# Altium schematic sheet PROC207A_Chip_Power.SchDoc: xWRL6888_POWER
size 431 x 279 mm; Date: Not shown in title block; ApprovedBy: Not shown in title block; CheckedBy: Not shown in title block; Author: Not shown in title block; CompanyName: Not shown in title block; DrawnBy: Mistral; Engineer: Not shown in title block; Organization: Not shown in title block; Address1: Not shown in title block; Address2: Not shown in title block; Address3: Not shown in title block; Address4: Not shown in title block; DocumentNumber: 2; Revision: Use project parameter SCH_Rev; SheetNumber: 7; SheetTotal: 18; PageSetup: Record=PageOptions¦CenterHorizontal=True¦CenterVertical=True¦PrintScale=1.00¦XCorrection=1.00¦YCorrection=1.00¦PrintKind=0¦BorderSize=5000000¦LeftOffset=0¦BottomOffset=0¦Orientation=2¦PaperLength=1000¦PaperWidth=1000¦Scale=100¦PaperSource=15¦PrintQuality=600¦MediaType=1¦DitherType=10¦PaperKind=Letter¦PrintScaleMode=1
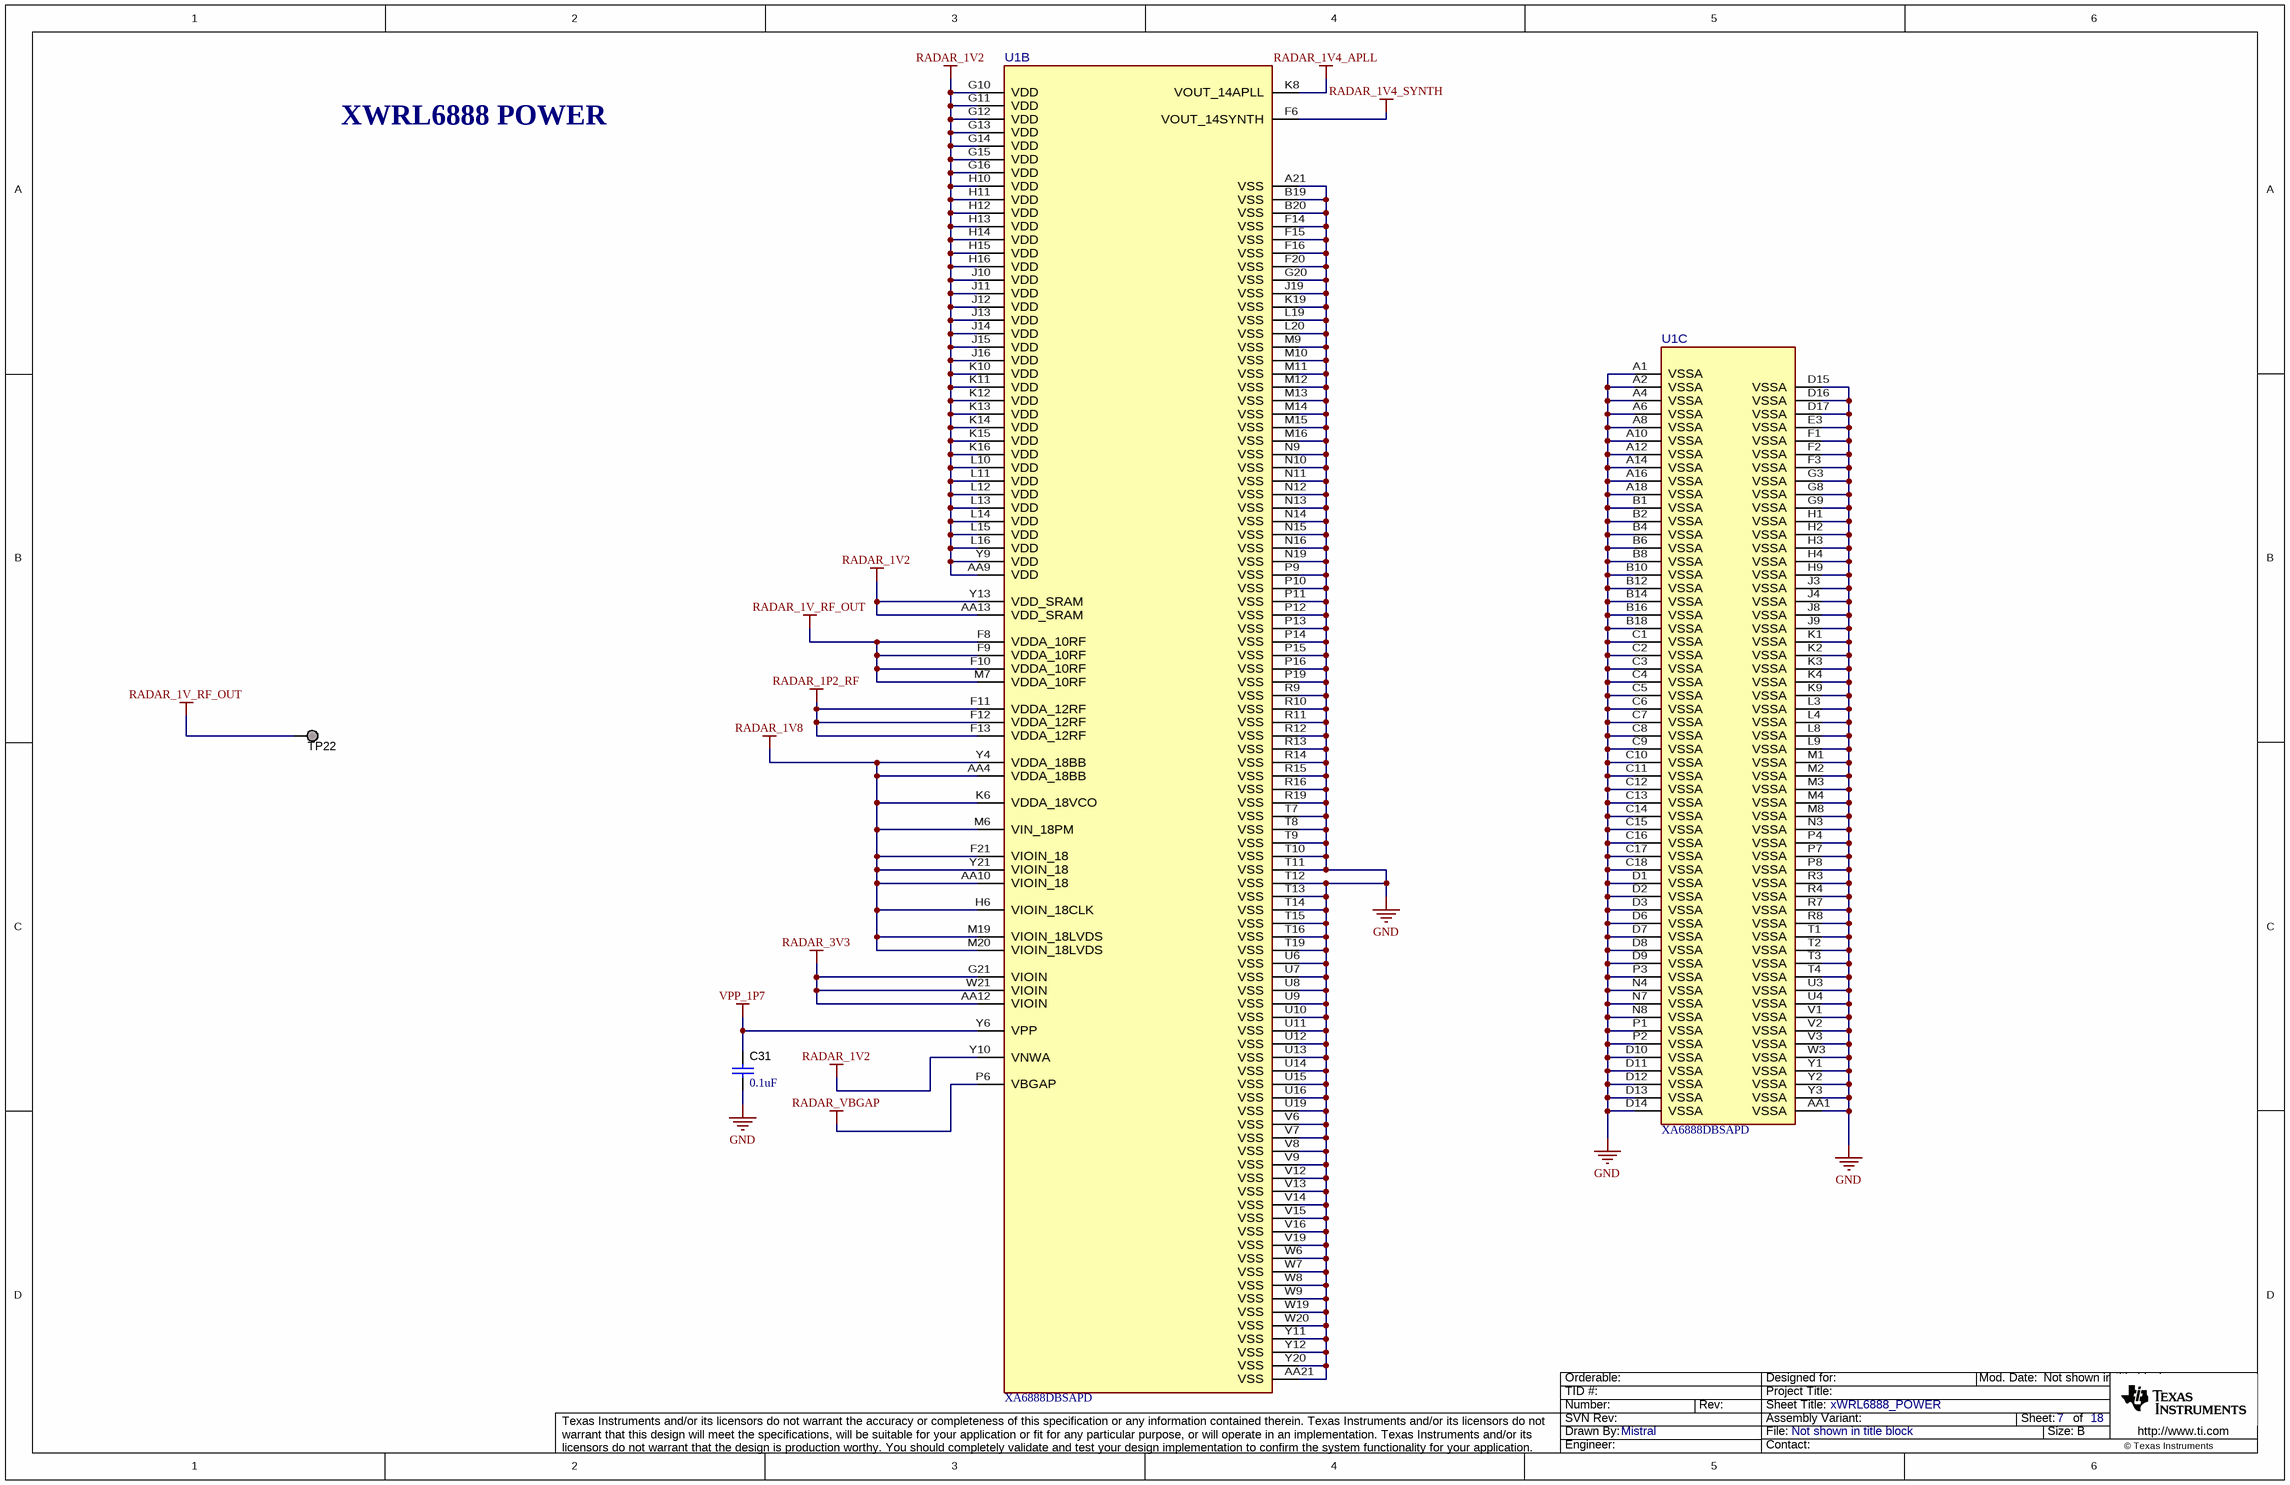
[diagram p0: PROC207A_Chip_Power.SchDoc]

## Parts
C31  ValueDisplayed: 0.1uF  [0402]  (hidden comment: GCM155R71H104KE02D)
TP22  TESTPOINT  [TP_VIA_060RND040]  (value not drawn)  (no BOM)
U1  XA6888DBSAPD  [0-MFG]  (parts B,C of 3)

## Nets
GND: C31.2 U1.A1(VSSA) U1.A2(VSSA) U1.A4(VSSA) U1.A6(VSSA) U1.A8(VSSA) U1.A10(VSSA) U1.A12(VSSA) U1.A14(VSSA) U1.A16(VSSA) U1.A18(VSSA) U1.A21(VSS) U1.AA1(VSSA) U1.AA21(VSS) U1.B1(VSSA) U1.B2(VSSA) U1.B4(VSSA) U1.B6(VSSA) U1.B8(VSSA) U1.B10(VSSA) U1.B12(VSSA) U1.B14(VSSA) U1.B16(VSSA) U1.B18(VSSA) U1.B19(VSS) U1.B20(VSS) U1.C1(VSSA) U1.C2(VSSA) U1.C3(VSSA) U1.C4(VSSA) U1.C5(VSSA) U1.C6(VSSA) U1.C7(VSSA) U1.C8(VSSA) U1.C9(VSSA) U1.C10(VSSA) U1.C11(VSSA) U1.C12(VSSA) U1.C13(VSSA) U1.C14(VSSA) U1.C15(VSSA) U1.C16(VSSA) U1.C17(VSSA) U1.C18(VSSA) U1.D1(VSSA) U1.D2(VSSA) U1.D3(VSSA) U1.D6(VSSA) U1.D7(VSSA) U1.D8(VSSA) U1.D9(VSSA) U1.D10(VSSA) U1.D11(VSSA) U1.D12(VSSA) U1.D13(VSSA) U1.D14(VSSA) U1.D15(VSSA) U1.D16(VSSA) U1.D17(VSSA) U1.E3(VSSA) U1.F1(VSSA) U1.F2(VSSA) U1.F3(VSSA) U1.F14(VSS) U1.F15(VSS) U1.F16(VSS) U1.F20(VSS) U1.G3(VSSA) U1.G8(VSSA) U1.G9(VSSA) U1.G20(VSS) U1.H1(VSSA) U1.H2(VSSA) U1.H3(VSSA) U1.H4(VSSA) U1.H9(VSSA) U1.J3(VSSA) U1.J4(VSSA) U1.J8(VSSA) U1.J9(VSSA) U1.J19(VSS) U1.K1(VSSA) U1.K2(VSSA) U1.K3(VSSA) U1.K4(VSSA) U1.K9(VSSA) U1.K19(VSS) U1.L3(VSSA) U1.L4(VSSA) U1.L8(VSSA) U1.L9(VSSA) U1.L19(VSS) U1.L20(VSS) U1.M1(VSSA) U1.M2(VSSA) U1.M3(VSSA) U1.M4(VSSA) U1.M8(VSSA) U1.M9(VSS) U1.M10(VSS) U1.M11(VSS) U1.M12(VSS) U1.M13(VSS) U1.M14(VSS) U1.M15(VSS) U1.M16(VSS) U1.N3(VSSA) U1.N4(VSSA) U1.N7(VSSA) U1.N8(VSSA) U1.N9(VSS) U1.N10(VSS) U1.N11(VSS) U1.N12(VSS) U1.N13(VSS) U1.N14(VSS) U1.N15(VSS) U1.N16(VSS) U1.N19(VSS) U1.P1(VSSA) U1.P2(VSSA) U1.P3(VSSA) U1.P4(VSSA) U1.P7(VSSA) U1.P8(VSSA) U1.P9(VSS) U1.P10(VSS) U1.P11(VSS) U1.P12(VSS) U1.P13(VSS) U1.P14(VSS) U1.P15(VSS) U1.P16(VSS) U1.P19(VSS) U1.R3(VSSA) U1.R4(VSSA) U1.R7(VSSA) U1.R8(VSSA) U1.R9(VSS) U1.R10(VSS) U1.R11(VSS) U1.R12(VSS) U1.R13(VSS) U1.R14(VSS) U1.R15(VSS) U1.R16(VSS) U1.R19(VSS) U1.T1(VSSA) U1.T2(VSSA) U1.T3(VSSA) U1.T4(VSSA) U1.T7(VSS) U1.T8(VSS) U1.T9(VSS) U1.T10(VSS) U1.T11(VSS) U1.T12(VSS) U1.T13(VSS) U1.T14(VSS) U1.T15(VSS) U1.T16(VSS) U1.T19(VSS) U1.U3(VSSA) U1.U4(VSSA) U1.U6(VSS) U1.U7(VSS) U1.U8(VSS) U1.U9(VSS) U1.U10(VSS) U1.U11(VSS) U1.U12(VSS) U1.U13(VSS) U1.U14(VSS) U1.U15(VSS) U1.U16(VSS) U1.U19(VSS) U1.V1(VSSA) U1.V2(VSSA) U1.V3(VSSA) U1.V6(VSS) U1.V7(VSS) U1.V8(VSS) U1.V9(VSS) U1.V12(VSS) U1.V13(VSS) U1.V14(VSS) U1.V15(VSS) U1.V16(VSS) U1.V19(VSS) U1.W3(VSSA) U1.W6(VSS) U1.W7(VSS) U1.W8(VSS) U1.W9(VSS) U1.W19(VSS) U1.W20(VSS) U1.Y1(VSSA) U1.Y2(VSSA) U1.Y3(VSSA) U1.Y11(VSS) U1.Y12(VSS) U1.Y20(VSS)
RADAR_1P2_RF: U1.F11(VDDA_12RF) U1.F12(VDDA_12RF) U1.F13(VDDA_12RF)
RADAR_1V2: U1.AA9(VDD) U1.AA13(VDD_SRAM) U1.G10(VDD) U1.G11(VDD) U1.G12(VDD) U1.G13(VDD) U1.G14(VDD) U1.G15(VDD) U1.G16(VDD) U1.H10(VDD) U1.H11(VDD) U1.H12(VDD) U1.H13(VDD) U1.H14(VDD) U1.H15(VDD) U1.H16(VDD) U1.J10(VDD) U1.J11(VDD) U1.J12(VDD) U1.J13(VDD) U1.J14(VDD) U1.J15(VDD) U1.J16(VDD) U1.K10(VDD) U1.K11(VDD) U1.K12(VDD) U1.K13(VDD) U1.K14(VDD) U1.K15(VDD) U1.K16(VDD) U1.L10(VDD) U1.L11(VDD) U1.L12(VDD) U1.L13(VDD) U1.L14(VDD) U1.L15(VDD) U1.L16(VDD) U1.Y9(VDD) U1.Y10(VNWA) U1.Y13(VDD_SRAM)
RADAR_1V4_APLL: U1.K8(VOUT_14APLL)
RADAR_1V4_SYNTH: U1.F6(VOUT_14SYNTH)
RADAR_1V8: U1.AA4(VDDA_18BB) U1.AA10(VIOIN_18) U1.F21(VIOIN_18) U1.H6(VIOIN_18CLK) U1.K6(VDDA_18VCO) U1.M6(VIN_18PM) U1.M19(VIOIN_18LVDS) U1.M20(VIOIN_18LVDS) U1.Y4(VDDA_18BB) U1.Y21(VIOIN_18)
RADAR_1V_RF_OUT: TP22.1 U1.F8(VDDA_10RF) U1.F9(VDDA_10RF) U1.F10(VDDA_10RF) U1.M7(VDDA_10RF)
RADAR_3V3: U1.AA12(VIOIN) U1.G21(VIOIN) U1.W21(VIOIN)
RADAR_VBGAP: U1.P6(VBGAP)
VPP_1P7: C31.1 U1.Y6(VPP)

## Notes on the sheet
- XWRL6888 POWER

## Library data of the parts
C31 = CMP-0006356-2: CAP, CERM, 0.1 uF, 50 V, +/- 10%, X7R, AEC-Q200 Grade 1, 0402; Manufacturer: MuRata; TaMin_C: -55°C; Polarized: N; SizeAreaWB_mm2: 3; Value1: Unknown; U/M: EA; Value: 0.1uF; TaMax_C: 125°C; SizeZ_mm: 0.6; SizeX_mm: 1; SizeY_mm: 0.5; Value2: 50V; AEC Qualified: Y; Cap_F: 100nF; AEC Category: Q200
TP22 = CMP-0078143-3: TEST POINT.  No entry in BOM.
U1 = CMP-0122984-4: Manufacturer: Texas Instruments; SizeZ_mm: 1.044mm; AEC Qualified: Unknown; Standoff Height: 0.155mm; AEC Category: Q200; CompType: IC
